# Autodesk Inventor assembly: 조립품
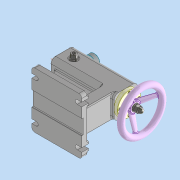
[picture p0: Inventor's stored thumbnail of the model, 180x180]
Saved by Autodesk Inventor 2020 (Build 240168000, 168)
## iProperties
Created: 2024-07
Part Number: 조립품
Document SubType Name: Assembly
Designer: oem
Author: oem
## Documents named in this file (15)
- C:\Users\oem\Desktop\740704V1010\조립품.iam
- C:\Users\oem\Desktop\740704V1010\본체.ipt
- C:\Users\oem\Desktop\740704V1010\부시.ipt
- C:\Users\oem\Desktop\740704V1010\슬리브.ipt
- C:\Users\oem\Desktop\740704V1010\나사축.ipt
- C:\Users\oem\Desktop\740704V1010\스러스트 볼 베어링 51101.ipt
- C:\Users\oem\Desktop\740704V1010\센터.ipt
- C:\Users\oem\Desktop\740704V1010\스톱퍼.ipt
- C:\Users\oem\Desktop\740704V1010\육각 소켓 머리 볼트 M6x12.ipt
- C:\Users\oem\Desktop\740704V1010\육각 소켓 머리 볼트 M12x16.ipt
- C:\Users\oem\Desktop\740704V1010\스프링  와셔 M12.ipt
- C:\Users\oem\Desktop\740704V1010\평와셔 M12.ipt
- C:\Users\oem\Desktop\740704V1010\평행키 4x4x14.ipt
- C:\Users\oem\Desktop\740704V1010\핸들.ipt
- C:\Users\oem\Desktop\740704V1010\캡너트 M12.ipt
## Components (1 placed, 1 different names)
1. 핸들:1
